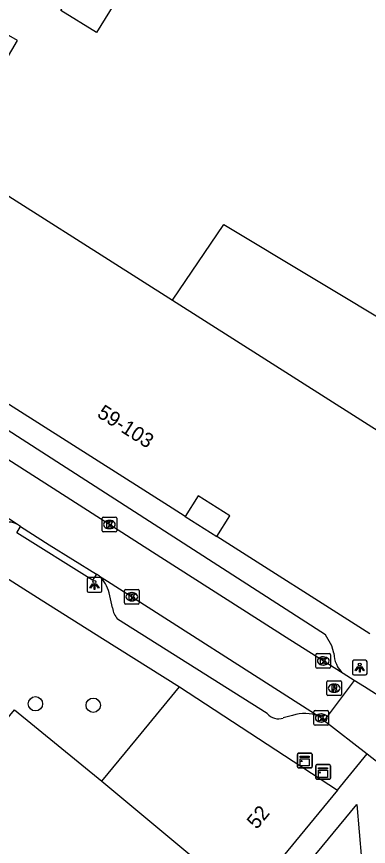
# Model space of a CAD drawing. Extents: x 160664 to 161506, y 382245 to 383288.
# Drawn here: x 161037.8 to 161061.8, y 383010 to 383066.6 of the extents above; entities that cross this region are included whole.
import ezdxf

# ---------------------------------------------------------------- set-up
doc = ezdxf.new("R2010")
doc.units = 0
for name, color, linetype in [('IMGEO_Boom', 7, 'Continuous'), ('IMGEO_Kast', 7, 'Continuous'), ('IMGEO_Kolk', 7, 'Continuous'), ('IMGEO_Lichtpunt', 7, 'Continuous'), ('IMGEO_Muur', 7, 'Continuous'), ('IMGEO_Pand', 7, 'Continuous'), ('IMGEO_Pand_nummerreeks', 7, 'Continuous'), ('IMGEO_Pand_overbouw', 7, 'Continuous'), ('IMGEO_Rijbaan_lokaal_open', 7, 'Continuous'), ('IMGEO_Rioolput', 7, 'Continuous'), ('IMGEO_Voetpad_open', 7, 'Continuous')]:
    doc.layers.add(name, color=color, linetype=linetype)

msp = doc.modelspace()

# ---------------------------------------------------------------- linework, layer by layer
at = {"layer": 'IMGEO_Boom'}
for centre in [(161039.102, 383019.684), (161043.043, 383019.585)]:
    msp.add_circle(centre, 0.489, dxfattribs=at)
at = {"layer": 'IMGEO_Kast'}
for p, q in [((161056.959, 383015.39), (161056.959, 383016.231)), ((161056.959, 383016.231), (161056.959, 383015.39)), ((161057.034, 383016.315), (161057.875, 383016.315)), ((161057.875, 383016.315), (161057.034, 383016.315)), ((161057.959, 383016.24), (161057.959, 383015.399)), ((161057.959, 383015.399), (161057.959, 383016.24)), ((161057.884, 383015.315), (161057.043, 383015.315)), ((161057.043, 383015.315), (161057.884, 383015.315)), ((161058.206, 383014.61), (161058.206, 383015.451)), ((161058.206, 383015.451), (161058.206, 383014.61)), ((161058.281, 383015.535), (161059.122, 383015.535)), ((161059.122, 383015.535), (161058.281, 383015.535)), ((161059.206, 383015.46), (161059.206, 383014.619)), ((161059.206, 383014.619), (161059.206, 383015.46)), ((161059.131, 383014.535), (161058.29, 383014.535)), ((161058.29, 383014.535), (161059.131, 383014.535))]:
    msp.add_line(p, q, dxfattribs=at)
for points in [[(161057.154, 383016.105), (161057.754, 383016.105), (161057.754, 383016.02), (161057.154, 383016.02), (161057.154, 383016.105)], [(161057.154, 383015.93), (161057.754, 383015.93), (161057.754, 383015.441), (161057.154, 383015.441), (161057.154, 383015.93)], [(161058.401, 383015.325), (161059.001, 383015.325), (161059.001, 383015.24), (161058.401, 383015.24), (161058.401, 383015.325)], [(161058.401, 383015.15), (161059.001, 383015.15), (161059.001, 383014.661), (161058.401, 383014.661), (161058.401, 383015.15)]]:
    msp.add_lwpolyline(points, dxfattribs=at)
for centre in [(161057.238, 383015.779), (161058.485, 383014.999)]:
    msp.add_circle(centre, 0.0377, dxfattribs=at)
for centre, start, end in [((161057.037, 383016.237), 92.4484, 184.2845), ((161057.037, 383016.237), 92.4484, 184.2845), ((161057.881, 383016.237), 2.4484, 94.2845), ((161057.881, 383016.237), 2.4484, 94.2845), ((161057.037, 383015.393), 182.4484, 274.2845), ((161057.037, 383015.393), 182.4484, 274.2845), ((161057.881, 383015.393), 272.4484, 4.2845), ((161057.881, 383015.393), 272.4484, 4.2845), ((161058.284, 383015.457), 92.4484, 184.2845), ((161058.284, 383015.457), 92.4484, 184.2845), ((161059.128, 383015.457), 2.4484, 94.2845), ((161059.128, 383015.457), 2.4484, 94.2845), ((161058.284, 383014.613), 182.4484, 274.2845), ((161058.284, 383014.613), 182.4484, 274.2845), ((161059.128, 383014.613), 272.4484, 4.2845), ((161059.128, 383014.613), 272.4484, 4.2845)]:
    msp.add_arc(centre, 0.0779, start, end, dxfattribs=at)
at = {"layer": 'IMGEO_Kolk'}
for p, q in [((161043.64, 383031.496), (161043.64, 383032.348)), ((161043.715, 383032.422), (161044.567, 383032.422)), ((161044.128, 383032.202), (161044.153, 383032.202)), ((161044.641, 383032.348), (161044.641, 383031.496)), ((161044.151, 383031.642), (161044.126, 383031.642)), ((161044.567, 383031.422), (161043.715, 383031.422)), ((161045.173, 383026.565), (161045.173, 383027.417)), ((161045.248, 383027.491), (161046.1, 383027.491)), ((161045.661, 383027.271), (161045.686, 383027.271)), ((161046.174, 383027.417), (161046.174, 383026.565)), ((161045.684, 383026.711), (161045.659, 383026.711)), ((161046.1, 383026.491), (161045.248, 383026.491)), ((161058.221, 383022.183), (161058.221, 383023.035)), ((161058.296, 383023.109), (161059.148, 383023.109)), ((161058.709, 383022.889), (161058.734, 383022.889)), ((161059.222, 383023.035), (161059.222, 383022.183)), ((161059.148, 383022.109), (161058.296, 383022.109)), ((161058.732, 383022.329), (161058.707, 383022.329)), ((161058.157, 383019.216), (161059.009, 383019.216)), ((161058.082, 383018.29), (161058.082, 383019.142)), ((161058.57, 383018.996), (161058.595, 383018.996)), ((161059.083, 383019.142), (161059.083, 383018.29)), ((161059.009, 383018.216), (161058.157, 383018.216)), ((161058.593, 383018.436), (161058.568, 383018.436))]:
    msp.add_line(p, q, dxfattribs=at)
for points in [[(161043.64, 383031.496), (161043.64, 383032.348)], [(161043.715, 383032.422), (161044.567, 383032.422)], [(161044.641, 383032.348), (161044.641, 383031.496)], [(161043.961, 383032.122), (161044.084, 383032.122), (161044.084, 383031.971), (161044.214, 383032.122), (161044.378, 383032.122), (161044.232, 383031.971), (161044.385, 383031.722), (161044.233, 383031.722), (161044.148, 383031.886), (161044.084, 383031.819), (161044.084, 383031.722), (161043.961, 383031.722), (161043.961, 383032.122)], [(161044.567, 383031.422), (161043.715, 383031.422)], [(161045.173, 383026.565), (161045.173, 383027.417)], [(161045.248, 383027.491), (161046.1, 383027.491)], [(161045.494, 383027.191), (161045.617, 383027.191), (161045.617, 383027.04), (161045.747, 383027.191), (161045.911, 383027.191), (161045.765, 383027.04), (161045.918, 383026.791), (161045.766, 383026.791), (161045.681, 383026.955), (161045.617, 383026.888), (161045.617, 383026.791), (161045.494, 383026.791), (161045.494, 383027.191)], [(161046.174, 383027.417), (161046.174, 383026.565)], [(161046.1, 383026.491), (161045.248, 383026.491)], [(161058.221, 383022.183), (161058.221, 383023.035)], [(161058.296, 383023.109), (161059.148, 383023.109)], [(161058.542, 383022.809), (161058.665, 383022.809), (161058.665, 383022.658), (161058.795, 383022.809), (161058.959, 383022.809), (161058.813, 383022.658), (161058.966, 383022.409), (161058.814, 383022.409), (161058.729, 383022.573), (161058.665, 383022.506), (161058.665, 383022.409), (161058.542, 383022.409), (161058.542, 383022.809)], [(161059.222, 383023.035), (161059.222, 383022.183)], [(161059.148, 383022.109), (161058.296, 383022.109)], [(161058.157, 383019.216), (161059.009, 383019.216)], [(161058.082, 383018.29), (161058.082, 383019.142)], [(161058.403, 383018.916), (161058.526, 383018.916), (161058.526, 383018.765), (161058.656, 383018.916), (161058.82, 383018.916), (161058.674, 383018.765), (161058.827, 383018.516), (161058.675, 383018.516), (161058.59, 383018.68), (161058.526, 383018.613), (161058.526, 383018.516), (161058.403, 383018.516), (161058.403, 383018.916)], [(161059.083, 383019.142), (161059.083, 383018.29)], [(161059.009, 383018.216), (161058.157, 383018.216)]]:
    msp.add_lwpolyline(points, dxfattribs=at)
for centre, start, end in [((161043.717, 383032.346), 91.552, 178.448), ((161043.717, 383032.346), 91.552, 178.448), ((161044.565, 383032.346), 1.552, 88.448), ((161044.565, 383032.346), 1.552, 88.448), ((161043.717, 383031.498), 181.552, 268.448), ((161043.717, 383031.498), 181.552, 268.448), ((161044.565, 383031.498), 271.552, 358.448), ((161044.565, 383031.498), 271.552, 358.448), ((161045.25, 383027.415), 91.552, 178.448), ((161045.25, 383027.415), 91.552, 178.448), ((161046.098, 383027.415), 1.552, 88.448), ((161046.098, 383027.415), 1.552, 88.448), ((161045.25, 383026.567), 181.552, 268.448), ((161045.25, 383026.567), 181.552, 268.448), ((161046.098, 383026.567), 271.552, 358.448), ((161046.098, 383026.567), 271.552, 358.448), ((161058.298, 383023.033), 91.552, 178.448), ((161058.298, 383023.033), 91.552, 178.448), ((161059.146, 383023.033), 1.552, 88.448), ((161059.146, 383023.033), 1.552, 88.448), ((161058.298, 383022.185), 181.552, 268.448), ((161058.298, 383022.185), 181.552, 268.448), ((161059.146, 383022.185), 271.552, 358.448), ((161059.146, 383022.185), 271.552, 358.448), ((161058.159, 383019.14), 91.552, 178.448), ((161058.159, 383019.14), 91.552, 178.448), ((161059.007, 383019.14), 1.552, 88.448), ((161059.007, 383019.14), 1.552, 88.448), ((161058.159, 383018.292), 181.552, 268.448), ((161058.159, 383018.292), 181.552, 268.448), ((161059.007, 383018.292), 271.552, 358.448), ((161059.007, 383018.292), 271.552, 358.448)]:
    msp.add_arc(centre, 0.0765, start, end, dxfattribs=at)
for centre, major_axis, ratio, start_param, end_param in [((161044.127, 383031.922), (-0.387, 0.002), 0.722429, 4.712389, 7.853982), ((161044.152, 383031.922), (-0.39, 0.002), 0.717154, 1.570796, 4.712389), ((161045.66, 383026.991), (-0.387, 0.002), 0.722429, 4.712389, 7.853982), ((161045.685, 383026.991), (-0.39, 0.002), 0.717154, 1.570796, 4.712389), ((161058.708, 383022.609), (-0.387, 0.002), 0.722429, 4.712389, 7.853982), ((161058.733, 383022.609), (-0.39, 0.002), 0.717154, 1.570796, 4.712389), ((161058.569, 383018.716), (-0.387, 0.002), 0.722429, 4.712389, 7.853982), ((161058.594, 383018.716), (-0.39, 0.002), 0.717154, 1.570796, 4.712389)]:
    msp.add_ellipse(centre, major_axis=major_axis, ratio=ratio, start_param=start_param, end_param=end_param, dxfattribs=at)
at = {"layer": 'IMGEO_Lichtpunt'}
for p, q in [((161043.527, 383028.296), (161042.719, 383028.296)), ((161043.527, 383028.296), (161042.719, 383028.296)), ((161042.625, 383028.201), (161042.625, 383027.394)), ((161042.625, 383028.201), (161042.625, 383027.394)), ((161043.621, 383027.394), (161043.621, 383028.201)), ((161043.621, 383027.394), (161043.621, 383028.201)), ((161042.719, 383027.3), (161043.527, 383027.3)), ((161042.719, 383027.3), (161043.527, 383027.3)), ((161061.606, 383022.655), (161060.798, 383022.655)), ((161061.606, 383022.655), (161060.798, 383022.655)), ((161060.704, 383022.56), (161060.704, 383021.753)), ((161060.704, 383022.56), (161060.704, 383021.753)), ((161061.7, 383021.753), (161061.7, 383022.56)), ((161061.7, 383021.753), (161061.7, 383022.56)), ((161060.798, 383021.659), (161061.606, 383021.659)), ((161060.798, 383021.659), (161061.606, 383021.659))]:
    msp.add_line(p, q, dxfattribs=at)
for points in [[(161042.999, 383027.865), (161043.038, 383027.837), (161042.85, 383027.575), (161042.812, 383027.602), (161042.999, 383027.865)], [(161043.101, 383027.817), (161043.148, 383027.817), (161043.148, 383027.495), (161043.101, 383027.495), (161043.101, 383027.817)], [(161043.211, 383027.837), (161043.249, 383027.864), (161043.436, 383027.602), (161043.397, 383027.574), (161043.211, 383027.837)], [(161061.078, 383022.224), (161061.117, 383022.196), (161060.929, 383021.934), (161060.891, 383021.961), (161061.078, 383022.224)], [(161061.18, 383022.176), (161061.227, 383022.176), (161061.227, 383021.854), (161061.18, 383021.854), (161061.18, 383022.176)], [(161061.29, 383022.196), (161061.328, 383022.223), (161061.515, 383021.961), (161061.476, 383021.933), (161061.29, 383022.196)]]:
    msp.add_lwpolyline(points, dxfattribs=at)
for centre in [(161043.124, 383027.999), (161061.203, 383022.358)]:
    msp.add_circle(centre, 0.0994, dxfattribs=at)
for centre, start, end in [((161042.719, 383028.201), 90, 180), ((161042.719, 383028.201), 90, 180), ((161043.527, 383028.201), 0, 90), ((161043.527, 383028.201), 0, 90), ((161042.719, 383027.394), 180, 270), ((161042.719, 383027.394), 180, 270), ((161043.527, 383027.394), 270, 0), ((161043.527, 383027.394), 270, 360), ((161060.798, 383022.56), 90, 180), ((161060.798, 383022.56), 90, 180), ((161061.606, 383022.56), 0, 90), ((161061.606, 383022.56), 0, 90), ((161060.798, 383021.753), 180, 270), ((161060.798, 383021.753), 180, 270), ((161061.606, 383021.753), 270, 0), ((161061.606, 383021.753), 270, 360)]:
    msp.add_arc(centre, 0.0946, start, end, dxfattribs=at)
at = {"layer": 'IMGEO_Muur'}
msp.add_lwpolyline([(161039.5, 383026.785), (161043.678, 383024.149)], dxfattribs=at)
at = {"layer": 'IMGEO_Pand'}
for points in [[(161045.276, 383071.139), (161046.337, 383070.488), (161043.275, 383065.494), (161040.826, 383066.996), (161043.889, 383071.99)], [(161025.238, 383048.281), (161031.36, 383056.746), (161032.578, 383055.865), (161033.282, 383056.839), (161033.159, 383056.928), (161037.886, 383064.946), (161033.964, 383067.181), (161029.085, 383058.618), (161027.911, 383059.467), (161029.876, 383062.184)], [(161027.134, 383046.913), (161029.664, 383050.891), (161033.411, 383056.782), (161048.444, 383047.224)], [(161048.444, 383047.224), (161051.939, 383052.395), (161064.119, 383045.068), (161066.763, 383043.403), (161067.496, 383044.618)], [(161048.444, 383047.224), (161063.216, 383037.832), (161068.328, 383034.587)], [(161049.305, 383032.471), (161048.411, 383033.039), (161026.98, 383046.672), (161027.134, 383046.913)], [(161051.456, 383031.102), (161052.358, 383032.519), (161050.201, 383033.88), (161049.305, 383032.471)], [(161061.89, 383024.465), (161051.456, 383031.102)], [(161043.618, 383014.393), (161045.979, 383017.263), (161048.921, 383020.84)], [(161048.921, 383020.84), (161059.678, 383013.78)], [(161035.066, 383007.264), (161033.307, 383008.711), (161032.628, 383007.886), (161028.208, 383011.521), (161028.345, 383011.687), (161031.521, 383015.548), (161033.334, 383015.724), (161034.176, 383015.032), (161037.672, 383019.283), (161043.618, 383014.393)], [(161043.618, 383014.393), (161053.588, 383006.099)], [(161059.678, 383013.78), (161053.757, 383006.58), (161053.828, 383006.391), (161053.588, 383006.099)]]:
    msp.add_lwpolyline(points, dxfattribs=at)
at = {"layer": 'IMGEO_Pand_overbouw'}
msp.add_lwpolyline([(161049.305, 383032.471), (161051.456, 383031.102), (161052.358, 383032.519), (161050.201, 383033.88)], close=True, dxfattribs=at)
at = {"layer": 'IMGEO_Rijbaan_lokaal_open'}
for points in [[(161060.074, 383021.752), (161056.443, 383024.051), (161047.653, 383029.663), (161039.174, 383035.116), (161030.766, 383040.479), (161023.767, 383045.113), (161017.137, 383049.948), (161012.017, 383053.67)], [(161037.89, 383031.927), (161031.195, 383036.275)], [(161038.093, 383031.787), (161037.89, 383031.927)], [(161038.093, 383031.787), (161040.038, 383030.538), (161043.259, 383028.541)], [(161043.475, 383028.393), (161043.259, 383028.541)], [(161043.475, 383028.393), (161044.007, 383028.061), (161058.437, 383018.811)], [(161060.814, 383021.283), (161060.074, 383021.752)], [(161060.814, 383021.283), (161058.789, 383018.556)], [(161058.789, 383018.556), (161058.587, 383018.715), (161058.437, 383018.811)]]:
    msp.add_lwpolyline(points, dxfattribs=at)
at = {"layer": 'IMGEO_Rioolput'}
for p, q in [((161058.962, 383020.324), (161058.962, 383021.176)), ((161059.037, 383021.25), (161059.889, 383021.25)), ((161059.45, 383021.03), (161059.475, 383021.03)), ((161059.963, 383021.176), (161059.963, 383020.324)), ((161059.473, 383020.47), (161059.448, 383020.47)), ((161059.889, 383020.25), (161059.037, 383020.25))]:
    msp.add_line(p, q, dxfattribs=at)
for points in [[(161058.962, 383020.324), (161058.962, 383021.176)], [(161059.037, 383021.25), (161059.889, 383021.25)], [(161059.551, 383020.948), (161059.299, 383020.95), (161059.299, 383020.55)], [(161059.963, 383021.176), (161059.963, 383020.324)], [(161059.299, 383020.55), (161059.423, 383020.55), (161059.423, 383020.712), (161059.434, 383020.712)], [(161059.477, 383020.869), (161059.423, 383020.869), (161059.423, 383020.788)], [(161059.423, 383020.788), (161059.475, 383020.788)], [(161059.481, 383020.683), (161059.552, 383020.55), (161059.692, 383020.55), (161059.627, 383020.676)], [(161059.889, 383020.25), (161059.037, 383020.25)]]:
    msp.add_lwpolyline(points, dxfattribs=at)
for centre, radius, start, end in [((161059.039, 383021.174), 0.0765, 91.552, 178.448), ((161059.039, 383021.174), 0.0765, 91.552, 178.448), ((161059.55, 383020.838), 0.109, 350.3612, 89.416), ((161059.887, 383021.174), 0.0765, 1.552, 88.448), ((161059.887, 383021.174), 0.0765, 1.552, 88.448), ((161059.039, 383020.326), 0.0765, 181.552, 268.448), ((161059.039, 383020.326), 0.0765, 181.552, 268.448), ((161059.433, 383020.659), 0.0533, 26.0293, 88.6989), ((161059.459, 383020.977), 0.19, 274.7715, 282.9687), ((161059.483, 383020.773), 0.0964, 77.0061, 93.1865), ((161059.497, 383020.83), 0.0378, 276.6634, 79.6772), ((161059.548, 383020.838), 0.112, 277.5842, 350.9817), ((161059.532, 383020.623), 0.108, 29.5134, 73.7905), ((161059.887, 383020.326), 0.0765, 271.552, 358.448), ((161059.887, 383020.326), 0.0765, 271.552, 358.448)]:
    msp.add_arc(centre, radius, start, end, dxfattribs=at)
for centre, major_axis, ratio, start_param, end_param in [((161059.449, 383020.75), (-0.387, 0.002), 0.722429, 4.712389, 7.853982), ((161059.474, 383020.75), (-0.39, 0.002), 0.717154, 1.570796, 4.712389)]:
    msp.add_ellipse(centre, major_axis=major_axis, ratio=ratio, start_param=start_param, end_param=end_param, dxfattribs=at)
at = {"layer": 'IMGEO_Voetpad_open'}
for points in [[(161059.441, 383023.143), (161059.314, 383023.651), (161058.871, 383024.388), (161026.498, 383045.25), (161014.924, 383053.146)], [(161019.187, 383039.602), (161021.951, 383037.858), (161025.283, 383035.755), (161036.108, 383028.925), (161039.5, 383026.785), (161043.678, 383024.149), (161048.921, 383020.84)], [(161049.305, 383032.471), (161051.456, 383031.102)], [(161043.259, 383028.541), (161042.993, 383028.118), (161037.827, 383031.364), (161038.093, 383031.787)], [(161044.355, 383026.224), (161044.122, 383027.259)], [(161054.903, 383019.021), (161044.706, 383025.469)], [(161064.782, 383019.236), (161063.032, 383019.896), (161061.522, 383020.835), (161060.814, 383021.283)], [(161056.616, 383018.88), (161055.994, 383018.716)], [(161058.789, 383018.556), (161061.708, 383016.259)], [(161059.678, 383013.78), (161061.708, 383016.259)], [(161061.708, 383016.259), (161062.859, 383015.353), (161063.468, 383008.572), (161062.045, 383006.867)], [(161061.476, 383007.21), (161055.845, 383006.558), (161061.005, 383012.821), (161061.476, 383007.21)]]:
    msp.add_lwpolyline(points, dxfattribs=at)
for centre, radius, start, end in [((161037.282, 383030.815), 1.267, 61.3505, 116.9031), ((161041.872, 383026.727), 2.312, 13.3049, 46.1087), ((161045.7, 383026.39), 1.355, 187.038, 222.8295), ((161061.322, 383023.159), 1.881, 180.4989, 228.4387), ((161055.664, 383019.639), 0.981, 219.0941, 289.6682), ((161057.446, 383016.716), 2.317, 64.6762, 110.9838)]:
    msp.add_arc(centre, radius, start, end, dxfattribs=at)

# ---------------------------------------------------------------- texts
at = {"layer": 'IMGEO_Pand_nummerreeks'}
for s, rotation, p in [('59-103', 327.5362, (161043.237, 383039.317)), ('52', 50.5675, (161054.186, 383011.069))]:
    msp.add_text(s, height=1, rotation=rotation, dxfattribs=at).set_placement(p)

doc.saveas('drawing.dxf')
